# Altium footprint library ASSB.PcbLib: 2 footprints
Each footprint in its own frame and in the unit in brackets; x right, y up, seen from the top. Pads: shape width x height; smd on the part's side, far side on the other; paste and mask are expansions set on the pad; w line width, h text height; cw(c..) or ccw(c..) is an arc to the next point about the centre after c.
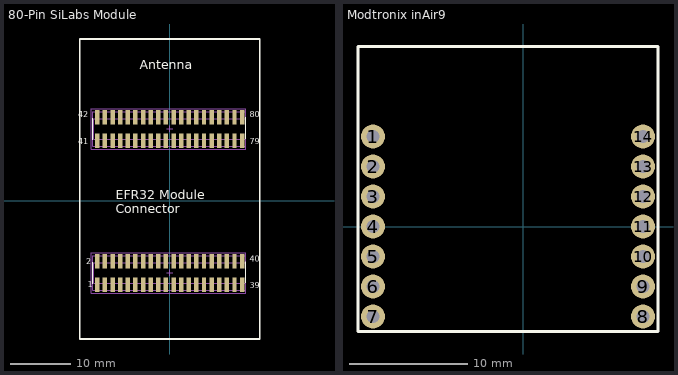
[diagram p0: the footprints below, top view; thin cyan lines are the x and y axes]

## 80-Pin SiLabs Module [mm] "Pin Header, pitch 1.27 mm, SMD, Vertical, dual row, 50p"
height 4.45
pads (80):
  rect 0.74x2.4 smd: 1(-12.065,-13.95) 2(-12.065,-10.05) 3(-10.795,-13.95) 4(-10.795,-10.05) 5(-9.525,-13.95) 6(-9.525,-10.05) 7(-8.255,-13.95) 8(-8.255,-10.05) 9(-6.985,-13.95) 10(-6.985,-10.05) 11(-5.715,-13.95) 12(-5.715,-10.05) 13(-4.445,-13.95) 14(-4.445,-10.05) 15(-3.175,-13.95) 16(-3.175,-10.05) 17(-1.905,-13.95) 18(-1.905,-10.05) 19(-0.635,-13.95) 20(-0.635,-10.05) 21(0.635,-13.95) 22(0.635,-10.05) 23(1.905,-13.95) 24(1.905,-10.05) 25(3.175,-13.95) 26(3.175,-10.05) 27(4.445,-13.95) 28(4.445,-10.05) 29(5.715,-13.95) 30(5.715,-10.05) 31(6.985,-13.95) 32(6.985,-10.05) 33(8.255,-13.95) 34(8.255,-10.05) 35(9.525,-13.95) 36(9.525,-10.05) 37(10.795,-13.95) 38(10.795,-10.05) 39(12.065,-13.95) 40(12.065,-10.05) 41(-12.065,10.066) 42(-12.065,13.966) 43(-10.795,10.066) 44(-10.795,13.966) 45(-9.525,10.066) 46(-9.525,13.966) 47(-8.255,10.066) 48(-8.255,13.966) 49(-6.985,10.066) 50(-6.985,13.966) 51(-5.715,10.066) 52(-5.715,13.966) 53(-4.445,10.066) 54(-4.445,13.966) 55(-3.175,10.066) 56(-3.175,13.966) 57(-1.905,10.066) 58(-1.905,13.966) 59(-0.635,10.066) 60(-0.635,13.966) 61(0.635,10.066) 62(0.635,13.966) 63(1.905,10.066) 64(1.905,13.966) 65(3.175,10.066) 66(3.175,13.966) 67(4.445,10.066) 68(4.445,13.966) 69(5.715,10.066) 70(5.715,13.966) 71(6.985,10.066) 72(6.985,13.966) 73(8.255,10.066) 74(8.255,13.966) 75(9.525,10.066) 76(9.525,13.966) 77(10.795,10.066) 78(10.795,13.966) 79(12.065,10.066) 80(12.065,13.966)
Top Overlay:
  lines w0.2: -12.85,-13.775 -12.85,-10.225 ; -12.85,10.241 -12.85,13.791 ; 12.7,-13.645 12.7,-10.095 ; 12.7,10.371 12.7,13.921
  lines w0.254: -15,-23 -15,27 15,27 15,-23 0,-23 -15,-23
  text "EFR32 Module / Connector" at -9,-2 h1.52
  text "41" at -15.24,9.476 h1
  text "42" at -15.24,13.921 h1
  text "79" at 13.335,9.476 h1
  text "80" at 13.335,13.921 h1
  text "40" at 13.335,-10.095 h1
  text "39" at 13.335,-14.54 h1
  text "2" at -13.925,-10.5 h1
  text "1" at -13.625,-14.4 h1
  text "Antenna" at -5,22 h1.52
Mechanical 11:
  lines w0.1: -12.7,-13.7 12.7,-13.7 12.7,-10.3 -12.7,-10.3 -12.7,-13.7 ; -12.7,10.316 -12.7,13.716 12.7,13.716 12.7,10.316 -12.7,10.316
Mechanical 13:
  lines w0.1: -12.85,-14.875 12.7,-14.875 12.7,-9.125 -12.85,-9.125 -12.85,-14.875 ; -12.85,9.141 -12.85,14.891 12.7,14.891 12.7,9.141 -12.85,9.141
Mechanical 15:
  lines w0.1: -0.5,-12 0.5,-12 ; -0.5,12.016 0.5,12.016 ; 0,-12.5 0,-11.5 ; 0,11.516 0,12.516 ; -13.05,-15.35 12.7,-15.35 12.7,-8.65 -13.05,-8.65 -13.05,-15.35 ; -13.05,8.666 -13.05,15.366 12.7,15.366 12.7,8.666 -13.05,8.666

## Modtronix inAir9 [mil] "Modtronix inAir9"
pads (14):
  round 80 hole 43.31: 1(-500,300) 2(-500,200) 3(-500,100) 4(-500,0) 5(-500,-100) 6(-500,-200) 7(-500,-300) 8(400,-300) 9(400,-200) 10(400,-100) 11(400,0) 12(400,100) 13(400,200) 14(400,300)
Top Overlay:
  lines w10: -550,-350 -550,600 450,600 450,-350 -550,-350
